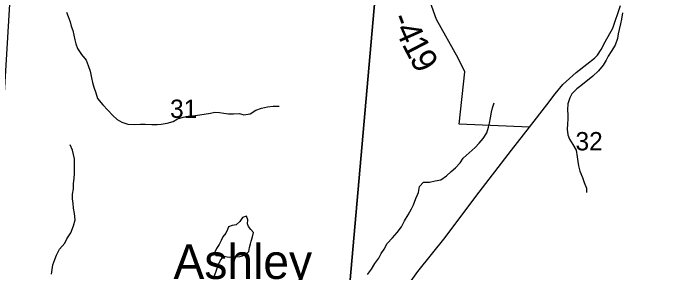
# Model space of a CAD drawing. Extents: x 1624196 to 2029251, y 146837 to 440034.
# Drawn here: x 1882613 to 1890429, y 281199 to 284322 of the extents above; entities that cross this region are included whole.
import ezdxf

# ---------------------------------------------------------------- set-up
doc = ezdxf.new("R2010")
doc.units = 0
for name, color, linetype in [('GM_X_Minor_Lake', 7, 'Continuous'), ('GM_X_Minor_River', 7, 'Continuous'), ('GM_X_Section', 7, 'Continuous'), ('GM_X_Section_Text', 7, 'Continuous'), ('GM_X_State_Route', 7, 'Continuous'), ('GM_X_Township_Road', 7, 'Continuous'), ('GM_X_Township_Road_Text', 7, 'Continuous'), ('GM_X_Unincorporated_Text', 7, 'Continuous')]:
    doc.layers.add(name, color=color, linetype=linetype)

msp = doc.modelspace()

# ---------------------------------------------------------------- linework, layer by layer
at = {"layer": 'GM_X_Minor_Lake'}
for points in [[(1885156, 281391.3), (1885226, 281379), (1885266.1, 281380.8), (1885304.1, 281382.6), (1885354.2, 281388.4), (1885384.3, 281394.3), (1885428.5, 281414.1), (1885460.7, 281448.1), (1885470.9, 281496.1), (1885481.1, 281540.2), (1885489.3, 281570.2), (1885505.5, 281622.3), (1885517.8, 281674.4), (1885487.9, 281712.6), (1885458, 281748.8), (1885448.1, 281779), (1885450.3, 281827.1), (1885432.5, 281871.3), (1885386.4, 281855.4), (1885368.5, 281831.5)], [(1885368.5, 281831.5), (1885352.1, 281809.5), (1885307.9, 281767.6), (1885261.8, 281759.8), (1885215.6, 281745.9), (1885203.5, 281713.9), (1885183.2, 281665.9), (1885149, 281621.9), (1885128.7, 281577.9), (1885104.5, 281529.9), (1885072.2, 281481.9), (1885050, 281439.9), (1885061.8, 281397.8), (1885109.9, 281395.5), (1885156, 281391.3)]]:
    msp.add_lwpolyline(points, dxfattribs=at)
at = {"layer": 'GM_X_Minor_River'}
for points in [[(1883258.1, 284333.3), (1883279.9, 284281.1), (1883303.7, 284216.8), (1883315.4, 284164.6), (1883335.2, 284112.4), (1883358.8, 284000), (1883372.6, 283949.8), (1883392.4, 283895.6), (1883442.1, 283821.2), (1883495.9, 283752.8), (1883523.7, 283688.5), (1883547.4, 283620.2), (1883563.1, 283539.9), (1883574.8, 283483.7), (1883588.6, 283429.6), (1883616.3, 283361.3), (1883636.1, 283291), (1883699.8, 283216.5), (1883759.6, 283150.1), (1883819.4, 283087.6), (1883873.3, 283037.3), (1883927.2, 283007), (1883999.2, 282980.6), (1884077.3, 282976.2), (1884153.5, 282979.9), (1884211.6, 282983.6), (1884291.7, 282979.2), (1884353.8, 282977), (1884403.9, 282980.7), (1884474, 282992.4), (1884548.2, 283014.2), (1884600.4, 283044), (1884668.6, 283065.7), (1884730.8, 283079.5), (1884782.9, 283083.3), (1884841, 283091), (1884923.2, 283102.7), (1884999.4, 283114.3), (1885053.5, 283126.1), (1885109.6, 283123.9), (1885159.6, 283113.6), (1885217.7, 283107.3), (1885275.8, 283107.1), (1885347.9, 283108.7), (1885403.9, 283092.4), (1885478.1, 283108.1), (1885546.4, 283151.9), (1885614.6, 283173.7), (1885686.8, 283191.4), (1885756.9, 283199.1), (1885829, 283196.8)], [(1889976.3, 284322.4), (1889962, 284248.3), (1889949.7, 284190.2), (1889935.4, 284124.1), (1889925.1, 284072), (1889916.9, 284015.9), (1889888.5, 283933.8), (1889838, 283855.9), (1889803.7, 283801.9), (1889779.5, 283751.9), (1889743.2, 283691.9), (1889686.8, 283624), (1889618.4, 283562.2), (1889473.6, 283442.5), (1889423.4, 283406.7), (1889365.1, 283348.8), (1889338.8, 283298.8), (1889314.4, 283226.7), (1889310.1, 283152.6), (1889313.9, 283094.4), (1889313.6, 283044.3), (1889309.4, 282982.1), (1889307.1, 282920), (1889316.8, 282851.8), (1889336.6, 282799.6), (1889374.4, 282735.2), (1889414.1, 282666.9), (1889427.8, 282588.6), (1889437.6, 282532.4), (1889445.3, 282480.3), (1889461.1, 282416), (1889490.8, 282339.7), (1889514.6, 282279.4), (1889540.3, 282209.1), (1889542.1, 282157)], [(1886897.6, 281168.8), (1886942, 281232.7), (1886984.3, 281300.7), (1887032.7, 281366.6), (1887061, 281422.6), (1887095.3, 281474.6), (1887131.6, 281542.6), (1887196, 281612.5), (1887254.4, 281674.4), (1887306.8, 281744.3), (1887343.2, 281816.3), (1887385.6, 281890.3), (1887425.9, 281960.3), (1887452.2, 282010.3), (1887480.6, 282086.4), (1887512.9, 282156.4), (1887525.3, 282228.5), (1887571.6, 282284.4), (1887643.7, 282282.1), (1887711.9, 282297.8), (1887782, 282311.5), (1887848.4, 282359.3), (1887906.7, 282409.2), (1887959, 282457.1), (1888013.3, 282517), (1888051.6, 282570.9), (1888122, 282636.8), (1888196.4, 282700.6), (1888244.7, 282754.5), (1888291, 282808.4), (1888335.4, 282876.4), (1888357.7, 282944.5), (1888368, 282994.5), (1888380.3, 283056.6), (1888392.6, 283124.8), (1888406.8, 283176.8), (1888427.1, 283238.9)], [(1883079.8, 281172.2), (1883088.1, 281228.3), (1883094.3, 281284.4), (1883118.7, 281350.5), (1883138.9, 281402.5), (1883177.3, 281474.5), (1883239.7, 281548.4), (1883266, 281598.5), (1883312.4, 281672.4), (1883342.8, 281756.5), (1883363.2, 281828.6), (1883355.5, 281904.8), (1883345.8, 281969), (1883342, 282027.2), (1883334.2, 282083.3), (1883332.5, 282139.5), (1883342.8, 282201.6), (1883345.1, 282265.8), (1883351.3, 282325.9), (1883357.6, 282386), (1883358.1, 282490.3), (1883356.4, 282564.5), (1883344.6, 282616.6), (1883330.8, 282666.8), (1883305.1, 282733.1)], [(1885048.7, 281153.2), (1885071.1, 281221.3), (1885093.4, 281281.3), (1885117.6, 281335.4), (1885156, 281391.3)]]:
    msp.add_lwpolyline(points, dxfattribs=at)
at = {"layer": 'GM_X_Section'}
for points in [[(1882678.2, 286082.9), (1887097.5, 285753.7), (1886621, 280376.8), (1882345.6, 280681.5), (1882574.5, 284429.1)], [(1887097.5, 285753.7), (1892530.6, 285317), (1892084.1, 279944), (1890624.3, 280055), (1886735, 280370.4), (1886621, 280376.8)]]:
    msp.add_lwpolyline(points, close=True, dxfattribs=at)
at = {"layer": 'GM_X_State_Route'}
msp.add_lwpolyline([(1886896.3, 280421.6), (1886904.5, 280427.1), (1887301, 280923.6), (1887504.2, 281205.7), (1887832, 281617.5), (1888203, 282110.7), (1888635.5, 282668.6), (1888852, 282944.7), (1889060.6, 283213.1), (1889162.6, 283348), (1889255, 283458.2), (1889333.8, 283530.7), (1889416.9, 283603.1), (1889544.3, 283706.2), (1889637.5, 283776.7), (1889673.8, 283814.2), (1889717, 283882.3), (1889764.5, 283975.6), (1889859.8, 284139.4), (1889950.9, 284410.8)], dxfattribs=at)
at = {"layer": 'GM_X_Township_Road'}
msp.add_lwpolyline([(1888852, 282944.7), (1888003.8, 282983), (1888072.3, 283614), (1887990.2, 283775.5), (1887727.6, 284244.3), (1887613.5, 284572.8)], dxfattribs=at)

# ---------------------------------------------------------------- texts
at = {"layer": 'GM_X_Section_Text'}
for s, p in [('31', (1884510.9, 283057.1)), ('32', (1889408.1, 282665.5))]:
    msp.add_text(s, height=221, rotation=0.00001, dxfattribs=at).set_placement(p)
at = {"layer": 'GM_X_Township_Road_Text'}
for s, rotation, p in [('-', 290.64709, (1887172.3, 284264.6)), ('4', 294.03201, (1887223.1, 284131.4)), ('1', 297.41695, (1887306.8, 283945.2)), ('9', 299.10941, (1887396.4, 283772.7))]:
    msp.add_text(s, height=300, rotation=rotation, dxfattribs=at).set_placement(p)
at = {"layer": 'GM_X_Unincorporated_Text'}
msp.add_text('Ashley', height=417, rotation=0.00001, dxfattribs=at).set_placement((1884552.7, 281116.2))

doc.saveas('drawing.dxf')
